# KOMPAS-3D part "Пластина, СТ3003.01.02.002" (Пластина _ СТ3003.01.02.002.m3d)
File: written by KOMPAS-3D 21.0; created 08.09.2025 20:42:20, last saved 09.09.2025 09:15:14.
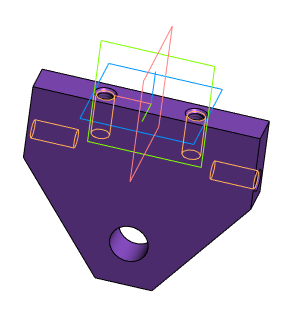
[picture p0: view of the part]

Document properties: Полное имя файла: C:\Users\1\Yandex.Disk\Документы\Новая папка\Стапель №2\Стапель _ СТ3003.00.00.000\Опора _ СТ3003.01.00.000\3D\Кронштейн _ СТ3003.01.02.000\Пластина _ СТ3003.01.02.002.m3d

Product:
- Part/product: Пластина  | designation СТ3003.01.02.002
    Материал: Лист$dБ-ПН-НО-16 ГОСТ 19903-2015;Ст3сп ГОСТ 14637-89$ (density 7850 kg/m3)
    Масса: 0.780129
    Форматы листов документа: A3

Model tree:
1. Эскиз:1
2. Элемент выдавливания:1
     Расстояние 1 = 16
3. Эскиз:18  (with: Элемент выдавливания:1)
4. ЛСК:13  (with: Плоскость XY, Плоскость ZX, Плоскость ZY, Ось X, Ось Y, Ось Z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)
     Ось X. Z = 1; Ось Y. X = 1; Ось Z. Y = 1; Координата X = 20; Точка начала. Х = 20
5. Эскиз:19
6. Элемент вращения:5
     Угол 1 = 360
7. Смещенная плоскость:5  (with: Элемент выдавливания:1)
     Расстояние = 0.923418
8. Условное изображение резьбы:5  (with: Элемент вращения:5)  (labels: 8x1,25)
     Длина резьбы = 19.0766; Шаг резьбы = 1.25; Номинальный диаметр резьбы = 8
9. Подгонка:5
10. Отверстие М8x20/1,6x45° (2)
11. Эскиз:23  (with: Элемент выдавливания:1)
12. ЛСК:17  (with: Плоскость XY, Плоскость ZX, Плоскость ZY, Ось X, Ось Y, Ось Z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)
     Ось X. Z = 1; Ось Y. X = 1; Ось Z. Y = 1; Координата X = -20; Точка начала. Х = -20
13. Эскиз:24
14. Элемент вращения:6
     Угол 1 = 360
15. Смещенная плоскость:6  (with: Элемент выдавливания:1)
     Расстояние = 0.923418
16. Условное изображение резьбы:6  (with: Элемент вращения:6)  (labels: 8x1,25)
     Длина резьбы = 19.0766; Шаг резьбы = 1.25; Номинальный диаметр резьбы = 8
17. Подгонка:6
18. Отверстие М8x20/1,6x45° (3)
19. Эскиз:10  (with: Элемент выдавливания:1)
20. ЛСК:7  (with: Плоскость XY, Плоскость ZX, Плоскость ZY, Ось X, Ось Y, Ось Z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)
     Ось X. X = -1; Ось Y. Y = 1; Ось Z. Z = -1; Координата X = -50; Координата Z = -25; Точка начала. Х = -50; Точка начала. Z = -25
21. Эскиз:11
22. Элемент вращения:3
     Угол 1 = 360
23. Смещенная плоскость:3  (with: Элемент выдавливания:1)
     Расстояние = 0.923418
24. Условное изображение резьбы:3  (with: Элемент вращения:3)  (labels: 8x1,25)
     Длина резьбы = 19.0766; Шаг резьбы = 1.25; Номинальный диаметр резьбы = 8
25. Подгонка:3
26. Отверстие М8x20/1,6x45°
27. Эскиз:14  (with: Элемент выдавливания:1)
28. ЛСК:10  (with: Плоскость XY, Плоскость ZX, Плоскость ZY, Ось X, Ось Y, Ось Z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)
     Ось X. X = 1; Ось Y. Y = 1; Ось Z. Z = 1; Координата X = 50; Координата Z = -25; Точка начала. Х = 50; Точка начала. Z = -25
29. Эскиз:15
30. Элемент вращения:4
     Угол 1 = 360
31. Смещенная плоскость:4  (with: Элемент выдавливания:1)
     Расстояние = 0.923418
32. Условное изображение резьбы:4  (with: Элемент вращения:4)  (labels: 8x1,25)
     Длина резьбы = 19.0766; Шаг резьбы = 1.25; Номинальный диаметр резьбы = 8
33. Подгонка:4
34. Отверстие М8x20/1,6x45° (1)  (labels: Лист$dБ-ПН-НО-16 ГОСТ 19903-2015;Ст3сп ГОСТ 14637-89$)

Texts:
  KTE.LIST=LTWD36N5dmSErgwNQxupvb
  Edge1
  Edge2
  СТ3003.01.02.002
